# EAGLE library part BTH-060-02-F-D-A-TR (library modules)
Samtec BTH-060-01-?-D-A-??
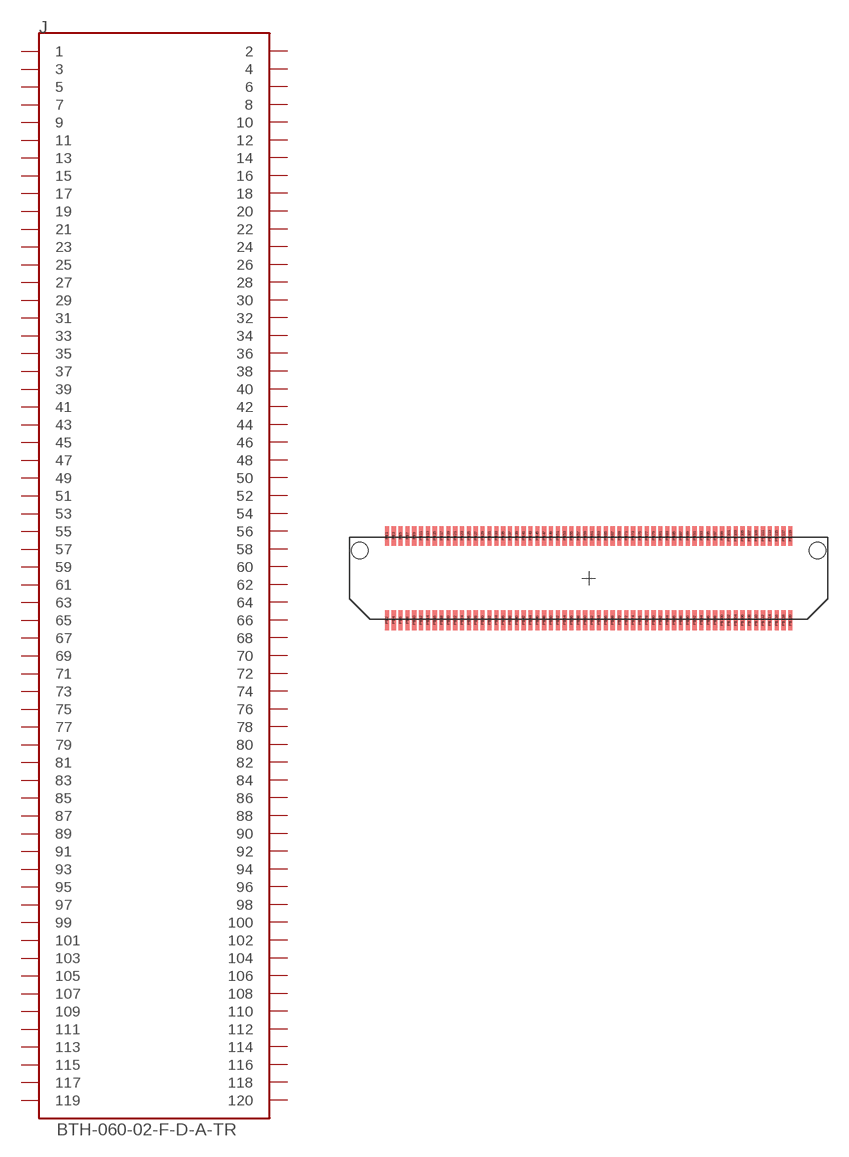
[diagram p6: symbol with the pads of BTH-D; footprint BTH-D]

Designator prefix J

## BTH-060-02-F-D-A-TR  [BTH-D]
P$1  1
P$2  2
P$3  3
P$4  4
P$5  5
P$6  6
P$7  7
P$8  8
P$9  9
P$10  10
P$11  11
P$12  12
P$13  13
P$14  14
P$15  15
P$16  16
P$17  17
P$18  18
P$19  19
P$20  20
P$21  21
P$22  22
P$23  23
P$24  24
P$25  25
P$26  26
P$27  27
P$28  28
P$29  29
P$30  30
P$31  31
P$32  32
P$33  33
P$34  34
P$35  35
P$36  36
P$37  37
P$38  38
P$39  39
P$40  40
P$41  41
P$42  42
P$43  43
P$44  44
P$45  45
P$46  46
P$47  47
P$48  48
P$49  49
P$50  50
P$51  51
P$52  52
P$53  53
P$54  54
P$55  55
P$56  56
P$57  57
P$58  58
P$59  59
P$60  60
P$61  61
P$62  62
P$63  63
P$64  64
P$65  65
P$66  66
P$67  67
P$68  68
P$69  69
P$70  70
P$71  71
P$72  72
P$73  73
P$74  74
P$75  75
P$76  76
P$77  77
P$78  78
P$79  79
P$80  80
P$81  81
P$82  82
P$83  83
P$84  84
P$85  85
P$86  86
P$87  87
P$88  88
P$89  89
P$90  90
P$91  91
P$92  92
P$93  93
P$94  94
P$95  95
P$96  96
P$97  97
P$98  98
P$99  99
P$100  100
P$101  101
P$102  102
P$103  103
P$104  104
P$105  105
P$106  106
P$107  107
P$108  108
P$109  109
P$110  110
P$111  111
P$112  112
P$113  113
P$114  114
P$115  115
P$116  116
P$117  117
P$118  118
P$119  119
P$120  120

## Footprint BTH-D (pad centres in mm)
smd 0.305 x 1.448: P$1 -14.753,3.086; P$2 -14.753,-3.086; P$3 -14.253,3.086; P$4 -14.253,-3.086; P$5 -13.753,3.086; P$6 -13.753,-3.086; P$7 -13.253,3.086; P$8 -13.253,-3.086; P$9 -12.753,3.086; P$10 -12.753,-3.086; P$11 -12.253,3.086; P$12 -12.253,-3.086; P$13 -11.753,3.086; P$14 -11.753,-3.086; P$15 -11.253,3.086; P$16 -11.253,-3.086; P$17 -10.753,3.086; P$18 -10.753,-3.086; P$19 -10.253,3.086; P$20 -10.253,-3.086; P$21 -9.753,3.086; P$22 -9.753,-3.086; P$23 -9.253,3.086; P$24 -9.253,-3.086; P$25 -8.753,3.086; P$26 -8.753,-3.086; P$27 -8.253,3.086; P$28 -8.253,-3.086; P$29 -7.753,3.086; P$30 -7.753,-3.086; P$31 -7.253,3.086; P$32 -7.253,-3.086; P$33 -6.753,3.086; P$34 -6.753,-3.086; P$35 -6.253,3.086; P$36 -6.253,-3.086; P$37 -5.753,3.086; P$38 -5.753,-3.086; P$39 -5.253,3.086; P$40 -5.253,-3.086; P$41 -4.753,3.086; P$42 -4.753,-3.086; P$43 -4.253,3.086; P$44 -4.253,-3.086; P$45 -3.753,3.086; P$46 -3.753,-3.086; P$47 -3.253,3.086; P$48 -3.253,-3.086; P$49 -2.753,3.086; P$50 -2.753,-3.086; P$51 -2.253,3.086; P$52 -2.253,-3.086; P$53 -1.753,3.086; P$54 -1.753,-3.086; P$55 -1.253,3.086; P$56 -1.253,-3.086; P$57 -0.753,3.086; P$58 -0.753,-3.086; P$59 -0.253,3.086; P$60 -0.253,-3.086; P$61 0.25,3.086; P$62 0.25,-3.086; P$63 0.75,3.086; P$64 0.75,-3.086; P$65 1.25,3.086; P$66 1.25,-3.086; P$67 1.75,3.086; P$68 1.75,-3.086; P$69 2.25,3.086; P$70 2.25,-3.086; P$71 2.75,3.086; P$72 2.75,-3.086; P$73 3.25,3.086; P$74 3.25,-3.086; P$75 3.75,3.086; P$76 3.75,-3.086; P$77 4.25,3.086; P$78 4.25,-3.086; P$79 4.75,3.086; P$80 4.75,-3.086; P$81 5.25,3.086; P$82 5.25,-3.086; P$83 5.75,3.086; P$84 5.75,-3.086; P$85 6.25,3.086; P$86 6.25,-3.086; P$87 6.75,3.086; P$88 6.75,-3.086; P$89 7.25,3.086; P$90 7.25,-3.086; P$91 7.75,3.086; P$92 7.75,-3.086; P$93 8.25,3.086; P$94 8.25,-3.086; P$95 8.75,3.086; P$96 8.75,-3.086; P$97 9.25,3.086; P$98 9.25,-3.086; P$99 9.75,3.086; P$100 9.75,-3.086; P$101 10.25,3.086; P$102 10.25,-3.086; P$103 10.75,3.086; P$104 10.75,-3.086; P$105 11.25,3.086; P$106 11.25,-3.086; P$107 11.75,3.086; P$108 11.75,-3.086; P$109 12.25,3.086; P$110 12.25,-3.086; P$111 12.75,3.086; P$112 12.75,-3.086; P$113 13.25,3.086; P$114 13.25,-3.086; P$115 13.75,3.086; P$116 13.75,-3.086; P$117 14.25,3.086; P$118 14.25,-3.086; P$119 14.75,3.086; P$120 14.75,-3.086
hole 1.2 at -16.738,2.032
hole 1.2 at 16.738,2.032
